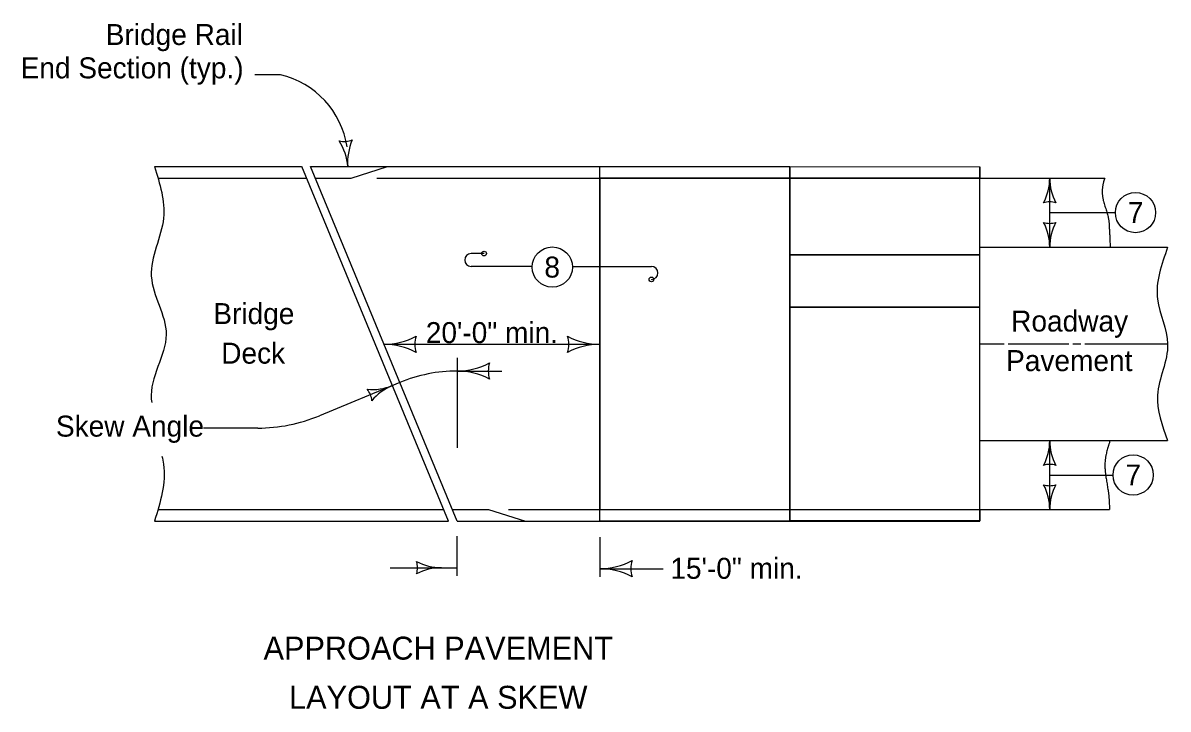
# Model space of a CAD drawing. Extents: x -2134860 to -2124557, y -2139046 to -2137324.
# Drawn here: x -2126534 to -2125661, y -2138229 to -2137706 of the extents above; entities that cross this region are included whole.
import ezdxf

# ---------------------------------------------------------------- set-up
doc = ezdxf.new("R2010")
doc.units = 0
for name, color, linetype in [('BridgeSuperStructureExisting', 7, 'Continuous'), ('dsnCellElements', 7, 'Continuous'), ('dsnStdLabel', 7, 'Continuous')]:
    doc.layers.add(name, color=color, linetype=linetype)

msp = doc.modelspace()

# ---------------------------------------------------------------- linework, layer by layer
at = {"layer": 'BridgeSuperStructureExisting'}
for p, q in [((-2126337.71, -2137745.6), (-2126357.21, -2137745.6)), ((-2126433.75, -2137815.7), (-2126321.65, -2137815.7)), ((-2126209.48, -2138086.06), (-2126321.47, -2137815.7)), ((-2126202.81, -2138086.06), (-2126314.79, -2137815.7)), ((-2126314.79, -2137815.7), (-2126094.13, -2137815.7)), ((-2126283.71, -2137824.41), (-2126256.03, -2137815.7)), ((-2126094.13, -2137877.15), (-2126094.13, -2137815.7)), ((-2126094.13, -2138077.2), (-2126094.13, -2137815.7)), ((-2126094.13, -2137815.7), (-2125804.31, -2137815.76)), ((-2125949.22, -2138086.08), (-2125949.22, -2137815.73)), ((-2125804.31, -2138086.11), (-2125804.31, -2137815.76)), ((-2125804.31, -2138086.11), (-2125804.31, -2137815.76)), ((-2126430.89, -2137824.41), (-2126317.95, -2137824.41)), ((-2126311.27, -2137824.41), (-2126283.71, -2137824.41)), ((-2126264.16, -2137824.41), (-2125708.97, -2137824.42)), ((-2125949.22, -2137824.44), (-2126094.13, -2137824.41)), ((-2125804.31, -2138077.19), (-2125804.31, -2137824.39)), ((-2125750.95, -2137877.15), (-2125750.95, -2137824.41)), ((-2125750.95, -2137850.75), (-2125721.48, -2137850.75)), ((-2125721.48, -2137850.75), (-2125700.92, -2137850.75)), ((-2126182.39, -2137882.02), (-2126192.22, -2137882.02)), ((-2125804.31, -2137877.19), (-2125661.02, -2137877.21)), ((-2126145.73, -2137891.86), (-2126192.21, -2137891.86)), ((-2126115.01, -2137891.86), (-2126054.71, -2137891.86)), ((-2126258.8, -2137951.23), (-2126094.13, -2137951.23)), ((-2126094.13, -2137951.23), (-2126094.13, -2137951.24)), ((-2126094.13, -2137951.24), (-2126094.13, -2138019.17)), ((-2126202.81, -2137961.59), (-2126202.81, -2138030.26)), ((-2126202.81, -2137971.6), (-2126168.84, -2137971.6)), ((-2126246.61, -2137980.32), (-2126308, -2138005.75)), ((-2126355.03, -2138015.11), (-2126396.45, -2138015.11)), ((-2126094.13, -2138019.17), (-2126094.13, -2138077.2)), ((-2126094.13, -2138086.06), (-2126094.13, -2138019.17)), ((-2125804.31, -2138024.65), (-2125661.02, -2138024.68)), ((-2125750.95, -2138077.24), (-2125750.95, -2138024.65)), ((-2125750.95, -2138050.92), (-2125721.48, -2138050.92)), ((-2125721.48, -2138050.92), (-2125702.7, -2138050.92)), ((-2126431.02, -2138077.2), (-2126213.15, -2138077.2)), ((-2126206.47, -2138077.2), (-2126178.91, -2138077.2)), ((-2126178.91, -2138077.2), (-2126150.78, -2138086.06)), ((-2126163.79, -2138077.2), (-2125705.3, -2138077.22)), ((-2126094.13, -2138077.2), (-2126043.64, -2138077.22)), ((-2126043.64, -2138077.21), (-2126043.64, -2138077.22)), ((-2126433.75, -2138086.06), (-2126209.48, -2138086.06)), ((-2126202.81, -2138086.06), (-2126094.13, -2138086.06)), ((-2126094.13, -2138086.06), (-2125804.31, -2138086.11)), ((-2126203.18, -2138097.62), (-2126203.18, -2138127.77)), ((-2126094.13, -2138098.35), (-2126094.13, -2138128.5)), ((-2126254.12, -2138121.63), (-2126203.18, -2138121.63)), ((-2126094.13, -2138122.36), (-2126045.74, -2138122.36))]:
    msp.add_line(p, q, dxfattribs=at)
for points in [[(-2126094.13, -2137824.41), (-2126094.13, -2137891.86), (-2126094.13, -2137951.23)], [(-2125949.22, -2138077.23), (-2125949.22, -2137950.76), (-2125949.22, -2137824.44)], [(-2125804.31, -2137950.88), (-2125785.62, -2137950.88)], [(-2125782.54, -2137950.88), (-2125736.46, -2137950.88)], [(-2125733.39, -2137950.88), (-2125727.25, -2137950.88)], [(-2125724.17, -2137950.88), (-2125661.01, -2137950.88)], [(-2126043.64, -2138077.22), (-2125995.99, -2138077.22), (-2125949.22, -2138077.23)]]:
    msp.add_lwpolyline(points, dxfattribs=at)
for centre in [(-2125685.56, -2137850.75), (-2126130.34, -2137892.33), (-2125687.34, -2138050.92)]:
    msp.add_circle(centre, 15.36, dxfattribs=at)
for centre, radius, start, end in [((-2126352.83, -2137810.52), 66.66, 8.48278, 76.88228), ((-2125791.12, -2137824.41), 40.18, 331.92751, 360), ((-2125710.77, -2137824.41), 40.18, 180, 208.07249), ((-2125750.95, -2137858.1), 15.52, 72.26665, 107.73335), ((-2125750.95, -2137843.46), 15.52, 252.26665, 287.73335), ((-2125791.12, -2137877.15), 40.18, 360, 28.07249), ((-2125710.77, -2137877.15), 40.18, 151.92751, 180), ((-2126192.22, -2137886.94), 4.92, 90, 270), ((-2126054.71, -2137896.77), 4.92, 270, 90), ((-2126258.8, -2137899.01), 52.23, 270, 298.07249), ((-2126258.8, -2138003.46), 52.23, 61.92751, 90), ((-2126215.01, -2137951.24), 20.17, 162.26665, 197.73335), ((-2126137.92, -2137951.24), 20.17, 342.26665, 17.73335), ((-2126094.13, -2137899.01), 52.23, 241.92751, 270), ((-2126094.13, -2138003.46), 52.23, 90, 118.07249), ((-2126202.81, -2137919.38), 52.23, 270, 298.07249), ((-2126202.81, -2137919.38), 52.23, 270, 298.07249), ((-2126159.02, -2137971.61), 20.17, 162.26665, 197.73335), ((-2126159.02, -2137971.61), 20.17, 162.26665, 197.73335), ((-2126202.81, -2138086.06), 114.45, 90, 112.5), ((-2126202.81, -2138023.84), 52.23, 61.92751, 90), ((-2126202.81, -2138023.84), 52.23, 61.92751, 90), ((-2126267.67, -2137945.56), 40.18, 264.4275, 292.49999), ((-2126283.42, -2137995.57), 15.52, 4.76664, 40.23334), ((-2126236.93, -2138019.8), 40.18, 112.49999, 140.57248), ((-2126355.03, -2137892.22), 122.89, 270, 292.49999), ((-2125791.12, -2138024.65), 40.18, 331.92751, 360), ((-2125710.77, -2138024.65), 40.18, 180, 208.07249), ((-2125750.95, -2138058.33), 15.52, 72.26665, 107.73335), ((-2125750.95, -2138043.55), 15.52, 252.26665, 287.73335), ((-2125791.12, -2138077.24), 40.18, 360, 28.07249), ((-2125710.77, -2138077.24), 40.18, 151.92751, 180), ((-2126083.82, -2138077.21), 40.18, 359.9859, 360), ((-2126248.62, -2138121.63), 15.52, 342.26665, 17.73335), ((-2126214.93, -2138081.46), 40.18, 241.92751, 270), ((-2126094.13, -2138070.13), 52.23, 270, 298.07249), ((-2126050.33, -2138122.36), 20.17, 162.26665, 197.73335), ((-2126214.93, -2138161.81), 40.18, 90, 118.07249), ((-2126094.13, -2138174.59), 52.23, 61.92751, 90)]:
    msp.add_arc(centre, radius, start, end, dxfattribs=at)
for points in [[(-2126433.74, -2137815.71), (-2126426.89, -2137854.91), (-2126436.17, -2137899.28), (-2126424.83, -2137943.64), (-2126436.17, -2137993.16), (-2126435.88, -2137995.55)], [(-2125661.02, -2137877.21), (-2125668.8, -2137916.88), (-2125661.02, -2137950.95), (-2125668.8, -2137990.13), (-2125661.02, -2138024.68)], [(-2126428.05, -2138036.47), (-2126426.89, -2138042.68), (-2126433.75, -2138086.06)]]:
    msp.add_spline(points, degree=3, dxfattribs=at)
for points in [[(-2125708.97, -2137824.41), (-2125709.15, -2137824.9), (-2125709.31, -2137825.39), (-2125709.47, -2137825.89), (-2125709.63, -2137826.38), (-2125709.76, -2137826.87), (-2125709.9, -2137827.37), (-2125710.16, -2137828.36), (-2125710.37, -2137829.34), (-2125710.54, -2137830.35), (-2125710.71, -2137831.34), (-2125710.82, -2137832.33), (-2125710.88, -2137833.34), (-2125710.91, -2137833.84), (-2125710.93, -2137834.33), (-2125710.93, -2137834.83), (-2125710.93, -2137835.33), (-2125710.92, -2137835.83), (-2125710.89, -2137836.34), (-2125710.83, -2137837.28), (-2125710.72, -2137838.22), (-2125710.56, -2137839.16), (-2125710.41, -2137840.11), (-2125710.23, -2137841.06), (-2125709.96, -2137841.98), (-2125709.41, -2137843.86), (-2125708.86, -2137845.74), (-2125708.3, -2137847.62), (-2125707.75, -2137849.51), (-2125707.2, -2137851.4), (-2125706.65, -2137853.29), (-2125706.38, -2137854.22), (-2125706.2, -2137855.18), (-2125706.05, -2137856.15), (-2125705.9, -2137857.11), (-2125705.78, -2137858.07), (-2125705.73, -2137859.04), (-2125705.65, -2137860.55), (-2125705.56, -2137862.06), (-2125705.49, -2137863.56), (-2125705.41, -2137865.07), (-2125705.33, -2137866.58), (-2125705.25, -2137868.09), (-2125705.18, -2137869.6), (-2125705.11, -2137871.11), (-2125705.05, -2137872.62), (-2125704.99, -2137874.13), (-2125704.94, -2137875.64), (-2125704.9, -2137877.15)], [(-2125704.9, -2138024.65), (-2125705.21, -2138025.52), (-2125705.52, -2138026.4), (-2125705.8, -2138027.28), (-2125706.08, -2138028.15), (-2125706.35, -2138029.03), (-2125706.62, -2138029.91), (-2125707.14, -2138031.65), (-2125707.58, -2138033.4), (-2125707.95, -2138035.19), (-2125708.49, -2138037.82), (-2125708.81, -2138040.48), (-2125708.88, -2138043.14), (-2125708.89, -2138043.59), (-2125708.89, -2138044.03), (-2125708.88, -2138044.47), (-2125708.86, -2138044.92), (-2125708.85, -2138045.36), (-2125708.83, -2138045.81), (-2125708.77, -2138046.8), (-2125708.68, -2138047.78), (-2125708.58, -2138048.77), (-2125708.47, -2138049.76), (-2125708.36, -2138050.75), (-2125708.21, -2138051.73), (-2125707.9, -2138053.7), (-2125707.58, -2138055.68), (-2125707.27, -2138057.65), (-2125706.95, -2138059.63), (-2125706.64, -2138061.61), (-2125706.33, -2138063.58), (-2125706.18, -2138064.57), (-2125706.06, -2138065.56), (-2125705.97, -2138066.56), (-2125705.87, -2138067.55), (-2125705.78, -2138068.54), (-2125705.73, -2138069.54), (-2125705.58, -2138072.1), (-2125705.44, -2138074.67), (-2125705.3, -2138077.24)]]:
    msp.add_open_spline(points, degree=3, dxfattribs=at)
at = {"layer": 'dsnCellElements'}
for centre in [(-2126182.39, -2137882.02), (-2126054.71, -2137901.69)]:
    msp.add_circle(centre, 1.78, dxfattribs=at)
for centre, radius, start, end in [((-2126289.09, -2137780.17), 16.42, 256.63311, 292.09982), ((-2126244, -2137812.46), 42.5, 156.29398, 184.36647), ((-2126328.75, -2137818.93), 42.5, 4.36647, 32.43895)]:
    msp.add_arc(centre, radius, start, end, dxfattribs=at)
at = {"layer": 'dsnStdLabel'}
for p, q in [((-2125804.31, -2137824.42), (-2125949.22, -2137824.42)), ((-2125949.22, -2137824.42), (-2125949.22, -2137882.97)), ((-2125804.31, -2137882.97), (-2125804.31, -2137824.42)), ((-2125804.31, -2137882.97), (-2125949.22, -2137882.97)), ((-2125949.22, -2137882.97), (-2125949.22, -2137922.97)), ((-2125949.22, -2137882.97), (-2125804.31, -2137882.97)), ((-2125804.31, -2137922.97), (-2125804.31, -2137882.97)), ((-2125804.31, -2137882.97), (-2125804.31, -2137882.97)), ((-2125949.22, -2137922.97), (-2125949.22, -2138077.22)), ((-2125949.22, -2137922.97), (-2125804.31, -2137922.97)), ((-2125804.31, -2138077.22), (-2125804.31, -2137922.97)), ((-2125949.22, -2138077.22), (-2125804.31, -2138077.22))]:
    msp.add_line(p, q, dxfattribs=at)
for points in [[(-2126094.13, -2137815.7), (-2125949.22, -2137815.73), (-2125949.22, -2137824.42), (-2126069.19, -2137824.41), (-2126094.13, -2137824.41)], [(-2125949.22, -2137815.73), (-2125804.31, -2137815.76), (-2125804.31, -2137824.44), (-2125924.28, -2137824.44), (-2125949.22, -2137824.44)], [(-2125949.22, -2138086.08), (-2126094.13, -2138086.06), (-2126094.13, -2138077.21), (-2126086.88, -2138077.21), (-2126043.64, -2138077.22), (-2125995.99, -2138077.22), (-2125949.22, -2138077.23)], [(-2125949.22, -2138077.19), (-2125804.31, -2138077.22), (-2125804.31, -2138085.91), (-2125924.28, -2138085.9), (-2125949.22, -2138085.9)]]:
    msp.add_lwpolyline(points, close=True, dxfattribs=at)
for points in [[(-2125804.31, -2137824.42), (-2125949.22, -2137824.42), (-2125949.22, -2137815.73), (-2125804.31, -2137815.76)], [(-2125804.31, -2137922.97), (-2125804.31, -2137922.97), (-2125949.22, -2137922.97)], [(-2125804.31, -2138086.11), (-2125949.22, -2138086.08), (-2125949.22, -2138077.22), (-2125804.31, -2138077.22)]]:
    msp.add_lwpolyline(points, dxfattribs=at)

# ---------------------------------------------------------------- texts
at = {"layer": 'BridgeSuperStructureExisting'}
for s, height, p in [('Bridge Rail', 16, (-2126470.93, -2137722.93)), ('End Section (typ.)', 16, (-2126535.86, -2137748.38)), ('APPROACH PAVEMENT', 17.5, (-2126350.59, -2138191.72)), ('LAYOUT AT A SKEW', 17.5, (-2126331.11, -2138229.22))]:
    msp.add_text(s, height=height, dxfattribs=at).set_placement(p)
at = {"layer": 'dsnStdLabel'}
for s, p in [('7', (-2125691.44, -2137858.75)), ('8', (-2126136.38, -2137900.33)), ('Bridge', (-2126388.89, -2137935.81)), ('Roadway', (-2125780.38, -2137941.49)), ('20\'-0" min.', (-2126226.83, -2137950.31)), ('Deck', (-2126382.85, -2137965.99)), ('Pavement', (-2125784.26, -2137971.67)), ('Skew Angle', (-2126508.94, -2138021.65)), ('7', (-2125693.23, -2138058.92)), ('15\'-0" min.', (-2126040.3, -2138130.09))]:
    msp.add_text(s, height=16, dxfattribs=at).set_placement(p)

doc.saveas('drawing.dxf')
